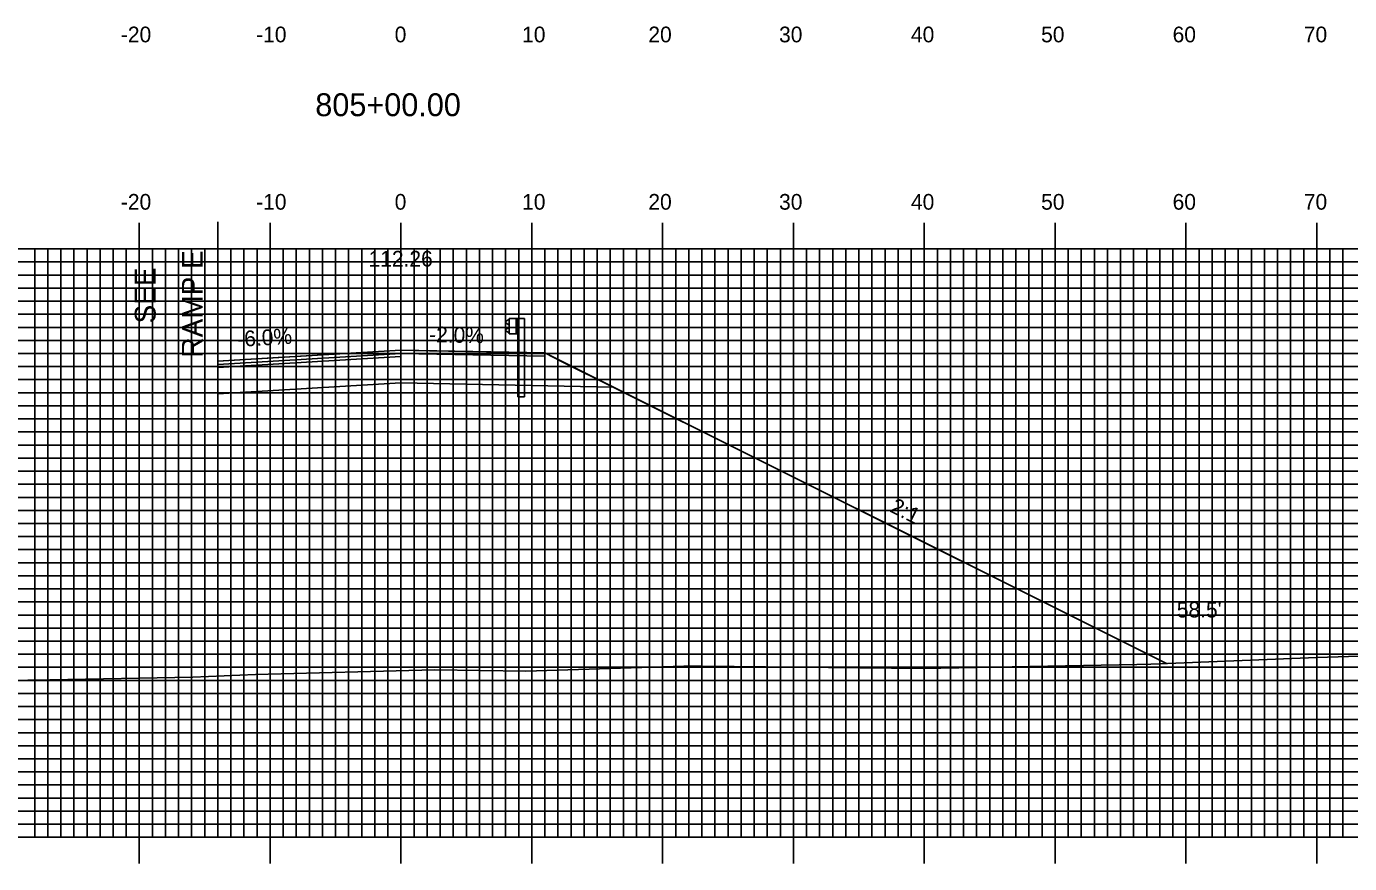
# Model space of a CAD drawing. Extents: x 485 to 829, y -1658 to -1438.
# Drawn here: x 622.5 to 723.6, y -1576.6 to -1512.6 of the extents above; entities that cross this region are included whole.
import ezdxf

# ---------------------------------------------------------------- set-up
doc = ezdxf.new("R2010")
doc.units = 0
for name, color, linetype in [('ANNOTATION', 7, 'Continuous'), ('D_Guardrail_Beam_Lt', 7, 'Continuous'), ('D_Roadway_Centerline', 7, 'Continuous'), ('D_Roadway_Centerline_Text', 7, 'Continuous'), ('D_Roadway_Edge_Shoulder', 7, 'Continuous'), ('D_Roadway_Edge_TW', 7, 'Continuous'), ('D_Roadway_Pavement', 7, 'Continuous'), ('D_Roadway_SlopeLines', 7, 'Continuous'), ('D_Roadway_SubGrade', 7, 'Continuous'), ('D_Text_Standard', 7, 'Continuous'), ('Default', 7, 'Continuous'), ('H_V ANNOTATION', 7, 'Continuous'), ('MAJOR', 7, 'Continuous'), ('MINOR', 7, 'Continuous'), ('S_Roadway_Centerline', 7, 'Continuous')]:
    doc.layers.add(name, color=color, linetype=linetype)

msp = doc.modelspace()

# ---------------------------------------------------------------- linework, layer by layer
at = {"layer": 'D_Guardrail_Beam_Lt'}
for p, q in [((659.31, -1535.02), (659.17, -1535.12)), ((659.4, -1535), (659.33, -1535.02)), ((659.4, -1534.92), (660.09, -1534.92)), ((659.4, -1536.09), (659.4, -1534.92)), ((659.93, -1534.92), (659.93, -1536.09)), ((660.03, -1534.92), (660.03, -1536.09)), ((660.09, -1534.92), (660.56, -1534.92)), ((660.09, -1534.92), (660.09, -1536.09)), ((660.56, -1534.92), (660.56, -1540.92)), ((659.17, -1535.27), (659.37, -1535.4)), ((659.37, -1535.6), (659.17, -1535.74)), ((659.17, -1535.88), (659.31, -1535.98)), ((659.33, -1535.99), (659.4, -1536)), ((659.4, -1535.47), (659.4, -1535.54)), ((660.09, -1536.09), (659.4, -1536.09)), ((660.07, -1540.92), (660.07, -1536.09)), ((660.07, -1540.92), (660.56, -1540.92))]:
    msp.add_line(p, q, dxfattribs=at)
for centre, major_axis, start_param, end_param in [((659.22, -1535.19), (-0.0877, 0), 5.323254, 7.243116), ((659.34, -1535.06), (-0.0417, 0), 4.907132, 5.323254), ((659.22, -1535.81), (-0.0877, 0), 5.323254, 7.243116), ((659.34, -1535.95), (-0.0417, 0), 0.959931, 1.376053), ((659.32, -1535.47), (0.0789, 0), 0, 0.959931), ((659.32, -1535.54), (0.0789, 0), 5.323254, 6.283185)]:
    msp.add_ellipse(centre, major_axis=major_axis, ratio=0.995501, start_param=start_param, end_param=end_param, dxfattribs=at)
at = {"layer": 'D_Roadway_Centerline'}
msp.add_lwpolyline([(637.13, -1538.18), (640.91, -1537.96), (651.13, -1537.34), (653.32, -1537.39), (659.13, -1537.5), (659.96, -1537.52), (662.13, -1537.56), (663.56, -1538.28), (667.34, -1540.17), (678.17, -1545.58), (709.64, -1561.32)], dxfattribs=at)
at = {"layer": 'D_Roadway_Edge_Shoulder'}
for points in [[(651.13, -1537.34), (659.13, -1537.5), (659.13, -1537.5), (662.13, -1537.56), (662.13, -1537.81), (651.13, -1537.59)], [(651.13, -1537.34), (662.13, -1537.56), (662.13, -1537.81), (651.13, -1537.59)]]:
    msp.add_lwpolyline(points, close=True, dxfattribs=at)
at = {"layer": 'D_Roadway_Edge_TW'}
msp.add_lwpolyline([(637.13, -1538.18), (651.13, -1537.34), (651.13, -1537.59), (637.13, -1538.43)], close=True, dxfattribs=at)
at = {"layer": 'D_Roadway_Pavement'}
msp.add_lwpolyline([(637.13, -1538.43), (651.13, -1537.59), (651.13, -1537.84), (637.13, -1538.68)], close=True, dxfattribs=at)
msp.add_lwpolyline([(651.13, -1537.59), (651.13, -1537.84)], dxfattribs=at)
msp.add_lwpolyline([(651.13, -1537.59), (651.13, -1537.84)], dxfattribs=at)
msp.add_lwpolyline([(651.13, -1537.59), (651.13, -1537.84)], dxfattribs=at)
at = {"layer": 'D_Roadway_SlopeLines'}
msp.add_lwpolyline([(662.13, -1537.56), (709.64, -1561.32)], dxfattribs=at)
msp.add_lwpolyline([(662.13, -1537.56), (709.64, -1561.32)], dxfattribs=at)
at = {"layer": 'D_Roadway_SubGrade'}
msp.add_line((637.13, -1527.54), (637.13, -1540.68), dxfattribs=at)
for points in [[(637.13, -1538.68), (651.13, -1537.84), (651.13, -1539.84), (637.13, -1540.68)], [(651.13, -1537.84), (651.13, -1537.59), (662.13, -1537.81), (662.13, -1537.56), (667.34, -1540.17), (651.13, -1539.84)]]:
    msp.add_lwpolyline(points, close=True, dxfattribs=at)
at = {"layer": 'Default'}
msp.add_line((637.13, -1540.68), (637.13, -1534.44), dxfattribs=at)
at = {"layer": 'MAJOR'}
for p, q in [((631.13, -1527.6), (631.13, -1529.6)), ((641.13, -1527.6), (641.13, -1529.6)), ((651.13, -1527.6), (651.13, -1529.6)), ((661.13, -1527.6), (661.13, -1529.6)), ((671.13, -1527.6), (671.13, -1529.6)), ((681.13, -1527.6), (681.13, -1529.6)), ((691.13, -1527.6), (691.13, -1529.6)), ((701.13, -1527.6), (701.13, -1529.6)), ((711.13, -1527.6), (711.13, -1529.6)), ((721.13, -1527.6), (721.13, -1529.6)), ((511.13, -1529.6), (791.13, -1529.6)), ((511.13, -1529.6), (791.13, -1529.6)), ((631.13, -1574.6), (631.13, -1529.6)), ((641.13, -1574.6), (641.13, -1529.6)), ((651.13, -1574.6), (651.13, -1529.6)), ((661.13, -1574.6), (661.13, -1529.6)), ((671.13, -1574.6), (671.13, -1529.6)), ((681.13, -1574.6), (681.13, -1529.6)), ((691.13, -1574.6), (691.13, -1529.6)), ((701.13, -1574.6), (701.13, -1529.6)), ((711.13, -1574.6), (711.13, -1529.6)), ((721.13, -1574.6), (721.13, -1529.6)), ((511.13, -1534.6), (791.13, -1534.6)), ((511.13, -1539.6), (791.13, -1539.6)), ((511.13, -1544.6), (791.13, -1544.6)), ((511.13, -1549.6), (791.13, -1549.6)), ((511.13, -1554.6), (791.13, -1554.6)), ((511.13, -1559.6), (791.13, -1559.6)), ((511.13, -1564.6), (791.13, -1564.6)), ((511.13, -1569.6), (791.13, -1569.6)), ((511.13, -1574.6), (791.13, -1574.6)), ((511.13, -1574.6), (791.13, -1574.6)), ((631.13, -1576.61), (631.13, -1574.6)), ((641.13, -1576.61), (641.13, -1574.6)), ((651.13, -1576.61), (651.13, -1574.6)), ((661.13, -1576.61), (661.13, -1574.6)), ((671.13, -1576.61), (671.13, -1574.6)), ((681.13, -1576.61), (681.13, -1574.6)), ((691.13, -1576.61), (691.13, -1574.6)), ((701.13, -1576.61), (701.13, -1574.6)), ((711.13, -1576.61), (711.13, -1574.6)), ((721.13, -1576.61), (721.13, -1574.6))]:
    msp.add_line(p, q, dxfattribs=at)
at = {"layer": 'MINOR'}
for p, q in [((623.13, -1574.6), (623.13, -1529.6)), ((624.13, -1574.6), (624.13, -1529.6)), ((625.13, -1574.6), (625.13, -1529.6)), ((626.13, -1574.6), (626.13, -1529.6)), ((627.13, -1574.6), (627.13, -1529.6)), ((628.13, -1574.6), (628.13, -1529.6)), ((629.13, -1574.6), (629.13, -1529.6)), ((630.13, -1574.6), (630.13, -1529.6)), ((632.13, -1574.6), (632.13, -1529.6)), ((633.13, -1574.6), (633.13, -1529.6)), ((634.13, -1574.6), (634.13, -1529.6)), ((635.13, -1574.6), (635.13, -1529.6)), ((636.13, -1574.6), (636.13, -1529.6)), ((637.13, -1574.6), (637.13, -1529.6)), ((638.13, -1574.6), (638.13, -1529.6)), ((639.13, -1574.6), (639.13, -1529.6)), ((640.13, -1574.6), (640.13, -1529.6)), ((642.13, -1574.6), (642.13, -1529.6)), ((643.13, -1574.6), (643.13, -1529.6)), ((644.13, -1574.6), (644.13, -1529.6)), ((645.13, -1574.6), (645.13, -1529.6)), ((646.13, -1574.6), (646.13, -1529.6)), ((647.13, -1574.6), (647.13, -1529.6)), ((648.13, -1574.6), (648.13, -1529.6)), ((649.13, -1574.6), (649.13, -1529.6)), ((650.13, -1574.6), (650.13, -1529.6)), ((652.13, -1574.6), (652.13, -1529.6)), ((653.13, -1574.6), (653.13, -1529.6)), ((654.13, -1574.6), (654.13, -1529.6)), ((655.13, -1574.6), (655.13, -1529.6)), ((656.13, -1574.6), (656.13, -1529.6)), ((657.13, -1574.6), (657.13, -1529.6)), ((658.13, -1574.6), (658.13, -1529.6)), ((659.13, -1574.6), (659.13, -1529.6)), ((660.13, -1574.6), (660.13, -1529.6)), ((662.13, -1574.6), (662.13, -1529.6)), ((663.13, -1574.6), (663.13, -1529.6)), ((664.13, -1574.6), (664.13, -1529.6)), ((665.13, -1574.6), (665.13, -1529.6)), ((666.13, -1574.6), (666.13, -1529.6)), ((667.13, -1574.6), (667.13, -1529.6)), ((668.13, -1574.6), (668.13, -1529.6)), ((669.13, -1574.6), (669.13, -1529.6)), ((670.13, -1574.6), (670.13, -1529.6)), ((672.13, -1574.6), (672.13, -1529.6)), ((673.13, -1574.6), (673.13, -1529.6)), ((674.13, -1574.6), (674.13, -1529.6)), ((675.13, -1574.6), (675.13, -1529.6)), ((676.13, -1574.6), (676.13, -1529.6)), ((677.13, -1574.6), (677.13, -1529.6)), ((678.13, -1574.6), (678.13, -1529.6)), ((679.13, -1574.6), (679.13, -1529.6)), ((680.13, -1574.6), (680.13, -1529.6)), ((682.13, -1574.6), (682.13, -1529.6)), ((683.13, -1574.6), (683.13, -1529.6)), ((684.13, -1574.6), (684.13, -1529.6)), ((685.13, -1574.6), (685.13, -1529.6)), ((686.13, -1574.6), (686.13, -1529.6)), ((687.13, -1574.6), (687.13, -1529.6)), ((688.13, -1574.6), (688.13, -1529.6)), ((689.13, -1574.6), (689.13, -1529.6)), ((690.13, -1574.6), (690.13, -1529.6)), ((692.13, -1574.6), (692.13, -1529.6)), ((693.13, -1574.6), (693.13, -1529.6)), ((694.13, -1574.6), (694.13, -1529.6)), ((695.13, -1574.6), (695.13, -1529.6)), ((696.13, -1574.6), (696.13, -1529.6)), ((697.13, -1574.6), (697.13, -1529.6)), ((698.13, -1574.6), (698.13, -1529.6)), ((699.13, -1574.6), (699.13, -1529.6)), ((700.13, -1574.6), (700.13, -1529.6)), ((702.13, -1574.6), (702.13, -1529.6)), ((703.13, -1574.6), (703.13, -1529.6)), ((704.13, -1574.6), (704.13, -1529.6)), ((705.13, -1574.6), (705.13, -1529.6)), ((706.13, -1574.6), (706.13, -1529.6)), ((707.13, -1574.6), (707.13, -1529.6)), ((708.13, -1574.6), (708.13, -1529.6)), ((709.13, -1574.6), (709.13, -1529.6)), ((710.13, -1574.6), (710.13, -1529.6)), ((712.13, -1574.6), (712.13, -1529.6)), ((713.13, -1574.6), (713.13, -1529.6)), ((714.13, -1574.6), (714.13, -1529.6)), ((715.13, -1574.6), (715.13, -1529.6)), ((716.13, -1574.6), (716.13, -1529.6)), ((717.13, -1574.6), (717.13, -1529.6)), ((718.13, -1574.6), (718.13, -1529.6)), ((719.13, -1574.6), (719.13, -1529.6)), ((720.13, -1574.6), (720.13, -1529.6)), ((722.13, -1574.6), (722.13, -1529.6)), ((723.13, -1574.6), (723.13, -1529.6)), ((511.13, -1530.6), (791.13, -1530.6)), ((511.13, -1531.6), (791.13, -1531.6)), ((511.13, -1532.6), (791.13, -1532.6)), ((511.13, -1533.6), (791.13, -1533.6)), ((511.13, -1535.6), (791.13, -1535.6)), ((511.13, -1536.6), (791.13, -1536.6)), ((511.13, -1537.6), (791.13, -1537.6)), ((511.13, -1538.6), (791.13, -1538.6)), ((511.13, -1540.6), (791.13, -1540.6)), ((511.13, -1541.6), (791.13, -1541.6)), ((511.13, -1542.6), (791.13, -1542.6)), ((511.13, -1543.6), (791.13, -1543.6)), ((511.13, -1545.6), (791.13, -1545.6)), ((511.13, -1546.6), (791.13, -1546.6)), ((511.13, -1547.6), (791.13, -1547.6)), ((511.13, -1548.6), (791.13, -1548.6)), ((511.13, -1550.6), (791.13, -1550.6)), ((511.13, -1551.6), (791.13, -1551.6)), ((511.13, -1552.6), (791.13, -1552.6)), ((511.13, -1553.6), (791.13, -1553.6)), ((511.13, -1555.6), (791.13, -1555.6)), ((511.13, -1556.6), (791.13, -1556.6)), ((511.13, -1557.6), (791.13, -1557.6)), ((511.13, -1558.6), (791.13, -1558.6)), ((511.13, -1560.6), (791.13, -1560.6)), ((511.13, -1561.6), (791.13, -1561.6)), ((511.13, -1562.6), (791.13, -1562.6)), ((511.13, -1563.6), (791.13, -1563.6)), ((511.13, -1565.6), (791.13, -1565.6)), ((511.13, -1566.6), (791.13, -1566.6)), ((511.13, -1567.6), (791.13, -1567.6)), ((511.13, -1568.6), (791.13, -1568.6)), ((511.13, -1570.6), (791.13, -1570.6)), ((511.13, -1571.6), (791.13, -1571.6)), ((511.13, -1572.6), (791.13, -1572.6)), ((511.13, -1573.6), (791.13, -1573.6))]:
    msp.add_line(p, q, dxfattribs=at)
at = {"layer": 'S_Roadway_Centerline'}
msp.add_lwpolyline([(615.91, -1562.69), (624.29, -1562.57), (635.21, -1562.36), (640.02, -1562.14), (653.7, -1561.78), (660.67, -1561.89), (672.76, -1561.52), (674.18, -1561.52), (691.05, -1561.68), (707.38, -1561.38), (708.44, -1561.35), (709.09, -1561.34), (721.14, -1560.85), (728.42, -1560.62), (733.48, -1560.61), (744.15, -1560.57), (745.48, -1560.57), (746.09, -1560.57), (748.34, -1560.42), (765.53, -1559.55), (778.36, -1559.61), (784.09, -1559.62), (791.13, -1559.17)], dxfattribs=at)

# ---------------------------------------------------------------- texts
at = {"layer": 'ANNOTATION'}
for s, height, rotation, p in [('RAMP E', 1.6, 90, (635.98, -1537.91)), ('SEE', 1.6, 90, (632.38, -1535.3)), ('-6.0%', 1.2, 3.4336, (638.65, -1537.1)), ('-2.0%', 1.2, 358.8576, (653.27, -1536.73)), ('2:1', 1.2, 333.4349, (688.43, -1549.67))]:
    msp.add_text(s, height=height, rotation=rotation, dxfattribs=at).set_placement(p)
at = {"layer": 'D_Roadway_Centerline_Text'}
msp.add_text('112.26', height=1.2, dxfattribs=at).set_placement((648.65, -1530.95))
at = {"layer": 'D_Text_Standard'}
msp.add_text("58.5'", height=1.2, dxfattribs=at).set_placement((710.43, -1557.79))
at = {"layer": 'H_V ANNOTATION'}
for s, height, p in [('-20', 1.2, (629.72, -1513.8)), ('-10', 1.2, (640.06, -1513.8)), ('0', 1.2, (650.65, -1513.8)), ('10', 1.2, (660.39, -1513.8)), ('20', 1.2, (670.04, -1513.8)), ('30', 1.2, (680.03, -1513.8)), ('40', 1.2, (690.11, -1513.8)), ('50', 1.2, (700.06, -1513.8)), ('60', 1.2, (710.11, -1513.8)), ('70', 1.2, (720.14, -1513.8)), ('805+00.00', 1.75, (644.58, -1519.45)), ('-20', 1.2, (629.72, -1526.6)), ('-10', 1.2, (640.06, -1526.6)), ('0', 1.2, (650.65, -1526.6)), ('10', 1.2, (660.39, -1526.6)), ('20', 1.2, (670.04, -1526.6)), ('30', 1.2, (680.03, -1526.6)), ('40', 1.2, (690.11, -1526.6)), ('50', 1.2, (700.06, -1526.6)), ('60', 1.2, (710.11, -1526.6)), ('70', 1.2, (720.14, -1526.6))]:
    msp.add_text(s, height=height, dxfattribs=at).set_placement(p)

doc.saveas('drawing.dxf')
